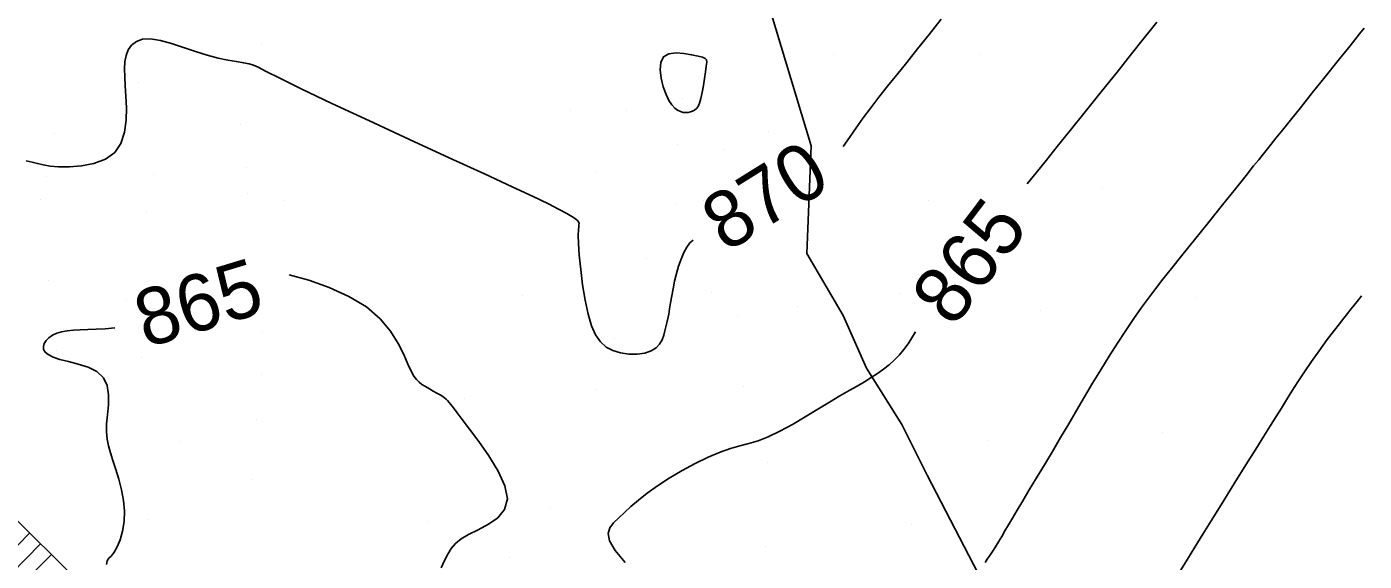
# Model space of a CAD drawing. Extents: x 400243 to 403697, y 4403637 to 4408083.
# Drawn here: x 402920.2 to 403096.7, y 4406350.8 to 4406421.4 of the extents above; entities that cross this region are included whole.
import ezdxf

# ---------------------------------------------------------------- set-up
doc = ezdxf.new("R2010")
doc.units = 0
doc.layers.add('HH_IC', color=7, linetype='Continuous')

msp = doc.modelspace()

# ---------------------------------------------------------------- linework, layer by layer
at = {"layer": 'HH_IC'}
for p, q in [((403023.67, 4406405.68), (403011.09, 4406447.46)), ((402951.13, 4406419.19), (402951.13, 4406419.19)), ((403026.58, 4406417.81), (403026.58, 4406417.81)), ((403045.96, 4406417.81), (403045.96, 4406417.81)), ((402934.95, 4406414.1), (402934.95, 4406414.1)), ((403006.67, 4406412), (403006.67, 4406412)), ((402991.86, 4406410.43), (402991.86, 4406410.43)), ((402999.3, 4406410.38), (402999.3, 4406410.38)), ((402948.3, 4406408.52), (402948.3, 4406408.52)), ((402923.85, 4406407.27), (402923.85, 4406407.27)), ((403018.08, 4406407.58), (403018.08, 4406407.58)), ((403006.08, 4406405.86), (403006.08, 4406405.86)), ((403012.28, 4406405.19), (403012.28, 4406405.19)), ((403023.12, 4406391.49), (403023.67, 4406405.68)), ((403023.67, 4406405.68), (403023.67, 4406405.68)), ((403083.59, 4406404.27), (403083.59, 4406404.27)), ((402949.15, 4406402.82), (402949.15, 4406402.82)), ((402922.79, 4406401.67), (402922.79, 4406401.67)), ((402936.93, 4406401.96), (402936.93, 4406401.96)), ((402995.26, 4406402.27), (402995.26, 4406402.27)), ((402949.25, 4406399.4), (402949.25, 4406399.4)), ((403062.14, 4406400.13), (403062.14, 4406400.13)), ((402921.95, 4406398.6), (402921.95, 4406398.6)), ((402954.01, 4406398.43), (402954.01, 4406398.43)), ((403005.9, 4406398.14), (403005.9, 4406398.14)), ((403009.42, 4406398.46), (403009.42, 4406398.46)), ((403039.18, 4406398.43), (403039.18, 4406398.43)), ((402935.92, 4406397.02), (402935.92, 4406397.02)), ((402992.32, 4406395.83), (402992.32, 4406395.83)), ((403002.01, 4406390.85), (403002.01, 4406390.85)), ((403023.12, 4406391.49), (403023.12, 4406391.49)), ((403027.89, 4406383.31), (403023.12, 4406391.49)), ((402923.08, 4406387.9), (402923.08, 4406387.9)), ((402933.32, 4406385.42), (402933.32, 4406385.42)), ((402985.64, 4406385.89), (402985.64, 4406385.89)), ((403010.52, 4406386.36), (403010.52, 4406386.36)), ((403035.46, 4406386.22), (403035.46, 4406386.22)), ((403074.6, 4406385.65), (403074.6, 4406385.65)), ((402950.91, 4406384.55), (402950.91, 4406384.55)), ((403013.92, 4406383.24), (403013.92, 4406383.24)), ((403021.84, 4406384.54), (403021.84, 4406384.54)), ((403027.89, 4406383.31), (403027.89, 4406383.31)), ((403030.99, 4406376.33), (403027.89, 4406383.31)), ((403053.9, 4406383.96), (403053.9, 4406383.96)), ((402951.32, 4406381.13), (402951.32, 4406381.13)), ((402997.79, 4406380.2), (402997.79, 4406380.2)), ((402924.06, 4406378.68), (402924.06, 4406378.68)), ((402935.26, 4406377.8), (402935.26, 4406377.8)), ((403030.99, 4406376.33), (403030.99, 4406376.33)), ((403035.67, 4406368.89), (403030.99, 4406376.33)), ((402951.18, 4406375.56), (402951.18, 4406375.56)), ((402995.19, 4406373.56), (402995.19, 4406373.56)), ((403014.7, 4406373.88), (403014.7, 4406373.88)), ((402977.9, 4406372.29), (402977.9, 4406372.29)), ((402937.32, 4406338.07), (402905.56, 4406369.26)), ((402950.44, 4406369.61), (402950.44, 4406369.61)), ((403035.67, 4406368.89), (403035.67, 4406368.89)), ((403038.98, 4406362.21), (403035.67, 4406368.89)), ((403070.08, 4406367.78), (403070.08, 4406367.78)), ((402940.39, 4406366.66), (402940.39, 4406366.66)), ((403046.94, 4406366.84), (403046.94, 4406366.84)), ((403017.89, 4406363.93), (403017.89, 4406363.93)), ((403038.98, 4406362.21), (403038.98, 4406362.21)), ((403061.46, 4406318.99), (403038.98, 4406362.21)), ((402950, 4406361.57), (402950, 4406361.57)), ((402989.29, 4406357.77), (402989.29, 4406357.77)), ((402936.03, 4406356.4), (402936.03, 4406356.4)), ((402973.22, 4406356.06), (402973.22, 4406356.06)), ((403036.96, 4406355.67), (403036.96, 4406355.67)), ((402921.97, 4406353.14), (402915.75, 4406346.81)), ((402917.47, 4406351.41), (402920.54, 4406354.54)), ((402920.25, 4406348.54), (402923.4, 4406351.74)), ((402983.92, 4406351.32), (402983.92, 4406351.32)), ((403017.68, 4406352.73), (403017.68, 4406352.73))]:
    msp.add_line(p, q, dxfattribs=at)
for points in [[(403027.91, 4406405.61), (403028.74, 4406406.81), (403029.62, 4406408.07), (403030.56, 4406409.38), (403031.55, 4406410.73), (403032.62, 4406412.12), (403033.77, 4406413.56), (403034.99, 4406415.09), (403036.32, 4406416.72), (403037.73, 4406418.49), (403039.25, 4406420.4), (403040.82, 4406422.41)], [(403052.21, 4406400.68), (403053.38, 4406402.15), (403054.68, 4406403.76), (403056.15, 4406405.6), (403057.86, 4406407.73), (403059.84, 4406410.2), (403061.95, 4406412.84), (403064.05, 4406415.45), (403065.96, 4406417.83), (403067.52, 4406419.79), (403068.62, 4406421.16), (403069.32, 4406422.03)], [(403046.63, 4406350.67), (403046.93, 4406351.1), (403047.26, 4406351.58), (403047.62, 4406352.14), (403048.01, 4406352.74), (403048.41, 4406353.4), (403048.83, 4406354.1), (403049.26, 4406354.83), (403049.73, 4406355.64), (403050.26, 4406356.54), (403050.88, 4406357.59), (403051.6, 4406358.82), (403052.46, 4406360.25), (403053.42, 4406361.84), (403054.46, 4406363.55), (403055.53, 4406365.34), (403056.61, 4406367.16), (403057.67, 4406368.97), (403058.72, 4406370.76), (403059.77, 4406372.55), (403060.83, 4406374.34), (403061.91, 4406376.12), (403063.01, 4406377.9), (403064.13, 4406379.65), (403065.23, 4406381.33), (403066.29, 4406382.9), (403067.28, 4406384.33), (403068.2, 4406385.6), (403069.11, 4406386.81), (403070.09, 4406388.07), (403071.23, 4406389.5), (403072.61, 4406391.22), (403074.28, 4406393.3), (403076.12, 4406395.59), (403077.97, 4406397.9), (403079.67, 4406400.03), (403081.08, 4406401.79), (403082.08, 4406403.04), (403082.75, 4406403.87), (403083.19, 4406404.42), (403083.54, 4406404.85), (403083.9, 4406405.31), (403084.38, 4406405.91), (403085.03, 4406406.71), (403085.87, 4406407.76), (403086.93, 4406409.09), (403088.25, 4406410.73), (403089.82, 4406412.69), (403091.53, 4406414.83), (403093.24, 4406416.96), (403094.8, 4406418.91), (403096.07, 4406420.5), (403096.68, 4406421.25)], [(402920.06, 4406403.73), (402920.86, 4406403.56), (402921.58, 4406403.36), (402922.34, 4406403.17), (402923.23, 4406403.02), (402924.36, 4406402.92), (402925.79, 4406402.91), (402927.39, 4406403.04), (402929.03, 4406403.37), (402930.53, 4406403.94), (402931.76, 4406404.82), (402932.59, 4406406.03), (402933.07, 4406407.49), (402933.28, 4406409.09), (402933.31, 4406410.72), (402933.24, 4406412.26), (402933.15, 4406413.63), (402933.08, 4406414.83), (402933.06, 4406415.88), (402933.11, 4406416.81), (402933.26, 4406417.64), (402933.55, 4406418.38), (402933.99, 4406419.01), (402934.62, 4406419.49), (402935.44, 4406419.77), (402936.5, 4406419.82), (402937.79, 4406419.61), (402939.26, 4406419.21), (402940.84, 4406418.7), (402942.43, 4406418.16), (402943.98, 4406417.67), (402945.42, 4406417.29), (402946.71, 4406417.02), (402947.83, 4406416.83), (402948.77, 4406416.68), (402949.5, 4406416.54), (402950.06, 4406416.37), (402950.71, 4406416.07), (402951.76, 4406415.53), (402953.55, 4406414.62), (402956.38, 4406413.23), (402960.44, 4406411.31), (402965.37, 4406409.01), (402970.69, 4406406.54), (402975.91, 4406404.13), (402980.55, 4406401.99), (402984.23, 4406400.29), (402986.99, 4406398.99), (402989.01, 4406398.02), (402990.43, 4406397.31), (402991.42, 4406396.78), (402992.11, 4406396.37), (402992.58, 4406396.04), (402992.87, 4406395.79), (402993.01, 4406395.59), (402993.05, 4406395.43), (402993.04, 4406395.28), (402993, 4406395.04), (402992.96, 4406394.62), (402992.94, 4406393.91), (402992.98, 4406392.81), (402993.08, 4406391.25), (402993.27, 4406389.37), (402993.52, 4406387.33), (402993.85, 4406385.31), (402994.24, 4406383.47), (402994.7, 4406381.94), (402995.24, 4406380.74), (402995.88, 4406379.82), (402996.64, 4406379.13), (402997.52, 4406378.65), (402998.54, 4406378.34), (402999.62, 4406378.18), (403000.71, 4406378.18), (403001.71, 4406378.33), (403002.57, 4406378.61), (403003.22, 4406379.02), (403003.68, 4406379.52), (403004, 4406380.09), (403004.22, 4406380.68), (403004.38, 4406381.26), (403004.52, 4406381.8), (403004.64, 4406382.33), (403004.76, 4406382.88), (403004.88, 4406383.48), (403005, 4406384.17), (403005.13, 4406384.98), (403005.28, 4406385.87), (403005.45, 4406386.83), (403005.65, 4406387.82), (403005.9, 4406388.83), (403006.19, 4406389.81), (403006.52, 4406390.74), (403006.89, 4406391.59), (403007.28, 4406392.31), (403007.69, 4406392.87), (403008.12, 4406393.25)], [(403009.13, 4406411.93), (403008.94, 4406411.32), (403008.75, 4406410.9), (403008.53, 4406410.61), (403008.3, 4406410.41), (403008.04, 4406410.28), (403007.76, 4406410.18), (403007.45, 4406410.11), (403007.13, 4406410.09), (403006.78, 4406410.12), (403006.42, 4406410.22), (403006.05, 4406410.39), (403005.68, 4406410.68), (403005.29, 4406411.1), (403004.91, 4406411.7), (403004.53, 4406412.5), (403004.17, 4406413.5), (403003.88, 4406414.62), (403003.74, 4406415.73), (403003.83, 4406416.72), (403004.2, 4406417.46), (403004.91, 4406417.86), (403005.85, 4406417.98), (403006.89, 4406417.91), (403007.91, 4406417.74), (403008.76, 4406417.54), (403009.35, 4406417.4), (403009.7, 4406417.25), (403009.87, 4406417.05), (403009.9, 4406416.73), (403009.84, 4406416.22), (403009.74, 4406415.49), (403009.62, 4406414.6), (403009.47, 4406413.65), (403009.31, 4406412.73), (403009.13, 4406411.93)], [(402954.81, 4406388.65), (402957.38, 4406387.96), (402960.08, 4406387.01), (402962.68, 4406385.82), (402964.98, 4406384.42), (402966.79, 4406382.86), (402968.17, 4406381.22), (402969.18, 4406379.6), (402969.92, 4406378.12), (402970.46, 4406376.88), (402970.9, 4406375.95), (402971.26, 4406375.28), (402971.59, 4406374.82), (402971.93, 4406374.48), (402972.31, 4406374.19), (402972.78, 4406373.9), (402973.29, 4406373.6), (402973.81, 4406373.31), (402974.3, 4406373.04), (402974.72, 4406372.8), (402975.05, 4406372.6), (402975.31, 4406372.42), (402975.51, 4406372.25), (402975.7, 4406372.06), (402975.89, 4406371.82), (402976.13, 4406371.52), (402976.46, 4406371.09), (402976.94, 4406370.45), (402977.63, 4406369.54), (402978.59, 4406368.28), (402979.82, 4406366.64), (402981.15, 4406364.74), (402982.37, 4406362.74), (402983.26, 4406360.79), (402983.59, 4406359.06), (402983.23, 4406357.67), (402982.33, 4406356.57), (402981.09, 4406355.71), (402979.73, 4406355), (402978.47, 4406354.38), (402977.48, 4406353.78), (402976.74, 4406353.16), (402976.18, 4406352.51), (402975.72, 4406351.77), (402975.3, 4406350.93), (402974.86, 4406349.98)], [(403072.41, 4406349.62), (403073.34, 4406351.13), (403074.3, 4406352.68), (403075.39, 4406354.43), (403076.68, 4406356.52), (403078.13, 4406358.85), (403079.62, 4406361.24), (403081.06, 4406363.56), (403082.35, 4406365.63), (403083.42, 4406367.35), (403084.3, 4406368.77), (403085.05, 4406369.97), (403085.74, 4406371.07), (403086.42, 4406372.16), (403087.14, 4406373.31), (403087.93, 4406374.54), (403088.78, 4406375.85), (403089.7, 4406377.22), (403090.71, 4406378.64), (403091.8, 4406380.12), (403092.91, 4406381.57), (403093.98, 4406382.94), (403094.94, 4406384.16), (403095.74, 4406385.16), (403096.23, 4406385.77), (403096.32, 4406385.88)], [(402930.69, 4406350.42), (402930.78, 4406350.88), (402931, 4406351.22), (402931.32, 4406351.55), (402931.69, 4406352.03), (402932.1, 4406352.74), (402932.48, 4406353.68), (402932.79, 4406354.81), (402933, 4406356.07), (402933.06, 4406357.43), (402932.94, 4406358.85), (402932.67, 4406360.27), (402932.32, 4406361.66), (402931.92, 4406362.96), (402931.53, 4406364.14), (402931.19, 4406365.17), (402930.93, 4406366.09), (402930.76, 4406366.98), (402930.68, 4406367.92), (402930.7, 4406368.98), (402930.81, 4406370.19), (402930.94, 4406371.5), (402930.96, 4406372.81), (402930.78, 4406374.04), (402930.28, 4406375.08), (402929.41, 4406375.88), (402928.25, 4406376.46), (402926.96, 4406376.88), (402925.67, 4406377.21), (402924.52, 4406377.5), (402923.63, 4406377.8), (402923, 4406378.12), (402922.59, 4406378.46), (402922.38, 4406378.82), (402922.35, 4406379.2), (402922.47, 4406379.59), (402922.71, 4406379.98), (402923.08, 4406380.35), (402923.55, 4406380.68), (402924.11, 4406380.95), (402924.76, 4406381.14), (402925.49, 4406381.27), (402926.31, 4406381.35), (402927.22, 4406381.39), (402928.22, 4406381.43), (402929.32, 4406381.47), (402930.5, 4406381.53), (402931.77, 4406381.65)], [(402999.12, 4406350.68), (402997.81, 4406352.27), (402997.08, 4406353.52), (402996.88, 4406354.48), (402997.09, 4406355.25), (402997.6, 4406355.91), (402998.28, 4406356.56), (402999.04, 4406357.27), (402999.9, 4406358.06), (403000.88, 4406358.91), (403002.03, 4406359.83), (403003.38, 4406360.8), (403004.94, 4406361.81), (403006.64, 4406362.81), (403008.39, 4406363.76), (403010.1, 4406364.59), (403011.67, 4406365.25), (403013.04, 4406365.72), (403014.28, 4406366.06), (403015.46, 4406366.37), (403016.68, 4406366.73), (403018.02, 4406367.25), (403019.55, 4406368), (403021.2, 4406368.91), (403022.89, 4406369.91), (403024.55, 4406370.92), (403026.1, 4406371.86), (403027.47, 4406372.67), (403028.68, 4406373.37), (403029.75, 4406373.98), (403030.72, 4406374.55), (403031.61, 4406375.09), (403032.45, 4406375.63), (403033.25, 4406376.2), (403033.99, 4406376.79), (403034.69, 4406377.42), (403035.33, 4406378.09), (403035.92, 4406378.81), (403036.47, 4406379.57), (403036.97, 4406380.35), (403037.45, 4406381.14)]]:
    msp.add_lwpolyline(points, dxfattribs=at)

# ---------------------------------------------------------------- texts
for s, rotation, p in [('870', 31.9843, (403012.44, 4406391.53)), ('865', 52.9464, (403042.45, 4406381.54)), ('865', 16.8968, (402935.86, 4406378.97))]:
    msp.add_text(s, height=7.5, rotation=rotation, dxfattribs=at).set_placement(p)

doc.saveas('drawing.dxf')
